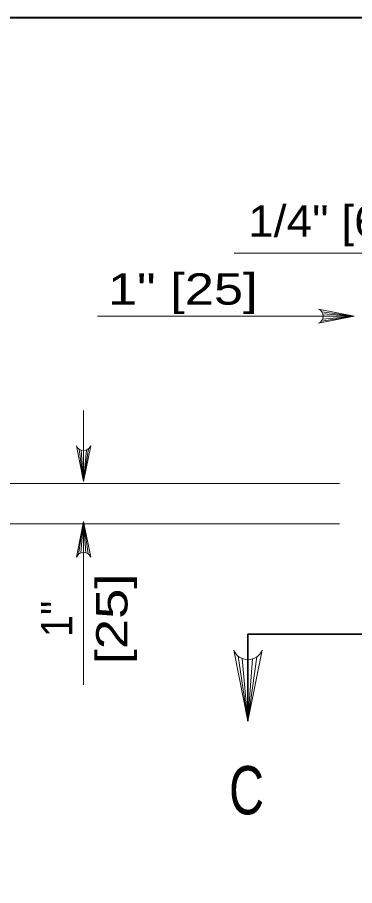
# Model space of a CAD drawing. Extents: x -410.5 to -376.5, y 1617.6 to 1661.6.
# Drawn here: x -396.459 to -394.78, y 1634.741 to 1639.062 of the extents above; entities that cross this region are included whole.
import ezdxf
from ezdxf.enums import TextEntityAlignment as Align

# ---------------------------------------------------------------- set-up
doc = ezdxf.new("R2010")
doc.units = 0
doc.header["$LTSCALE"] = 0.062
doc.layers.add('1', color=7, linetype='Continuous', lineweight=13)

msp = doc.modelspace()

# ---------------------------------------------------------------- linework, layer by layer
at = {"layer": '1', "lineweight": 25}
msp.add_line((-408.45475, 1639.06183), (-376.95475, 1639.06183), dxfattribs=at)
at = {"layer": '1'}
for p, q in [((-395.37925, 1637.88875), (-394.1165, 1637.88875)), ((-394.78308, 1637.57492), (-396.05983, 1637.57492)), ((-394.94525, 1637.55017), (-394.78308, 1637.57492)), ((-394.94333, 1637.59733), (-394.78308, 1637.57492)), ((-394.93908, 1637.56058), (-394.78308, 1637.57492)), ((-394.93792, 1637.58625), (-394.78308, 1637.57492)), ((-394.93625, 1637.57492), (-394.78308, 1637.57492)), ((-396.12908, 1636.75275), (-396.12908, 1637.10483)), ((-396.1515, 1636.913), (-396.12908, 1636.75275)), ((-396.14042, 1636.90758), (-396.12908, 1636.75275)), ((-396.10433, 1636.91483), (-396.12908, 1636.75275)), ((-396.11475, 1636.90875), (-396.12908, 1636.75275)), ((-396.12908, 1636.90592), (-396.12908, 1636.75275)), ((-400.65567, 1636.74175), (-394.85592, 1636.74175)), ((-400.65567, 1636.54183), (-394.85592, 1636.54183)), ((-396.15392, 1636.39075), (-396.12908, 1636.55283)), ((-396.1435, 1636.39683), (-396.12908, 1636.55283)), ((-396.12908, 1636.55283), (-396.12908, 1635.74108)), ((-396.12908, 1636.39967), (-396.12908, 1636.55283)), ((-396.11775, 1636.398), (-396.12908, 1636.55283)), ((-396.10667, 1636.39258), (-396.12908, 1636.55283)), ((-395.36058, 1635.88375), (-395.311, 1635.5595)), ((-395.33983, 1635.8715), (-395.311, 1635.5595)), ((-395.26617, 1635.88), (-395.311, 1635.5595)), ((-395.28833, 1635.86908), (-395.311, 1635.5595)), ((-395.311, 1635.86583), (-395.311, 1635.5595))]:
    msp.add_line(p, q, dxfattribs=at)
at = {"layer": '1', "lineweight": 35}
for q in [(-395.311, 1635.5595), (-393.8645, 1635.99217)]:
    msp.add_line((-395.311, 1635.99217), q, dxfattribs=at)
at = {"layer": '1', "lineweight": 40}
msp.add_lwpolyline([(-408.45475, 1639.06183), (-376.95475, 1639.06183), (-376.95475, 1618.06183), (-408.45475, 1618.06183)], close=True, dxfattribs=at)
msp.add_lwpolyline([(-408.45475, 1639.06183), (-376.95475, 1639.06183), (-376.95475, 1618.06183), (-408.45475, 1618.06183)], close=True, dxfattribs=at)
at = {"layer": '1'}
for points in [[(-394.96008, 1637.53958), (-394.78308, 1637.57492), (-394.96008, 1637.61033)], [(-396.09375, 1636.92975), (-396.12908, 1636.75275), (-396.1645, 1636.92975)], [(-396.1645, 1636.37583), (-396.12908, 1636.55283), (-396.09375, 1636.37583)], [(-395.38183, 1635.9135), (-395.311, 1635.5595), (-395.24025, 1635.9135)]]:
    msp.add_lwpolyline(points, dxfattribs=at)
for centre, radius, start, end in [((-394.97441, 1637.57499), 0.0382, 292.08605, 67.91218), ((-396.12915, 1636.94403), 0.0382, 202.08782, 337.91395), ((-396.12907, 1636.36155), 0.0382, 22.08782, 157.91395), ((-395.31095, 1635.94207), 0.0764, 202.08605, 337.91218)]:
    msp.add_arc(centre, radius, start, end, dxfattribs=at)

# ---------------------------------------------------------------- texts
for s, width, p in [('1/4" [6]', 1.1, (-395.3105, 1637.97025)), ('1" [25]', 1.25, (-396.008, 1637.63217))]:
    msp.add_text(s, height=0.156, dxfattribs=dict(at, width=width)).set_placement(p)
for s, width, p in [('[25]', 1.3, (-395.91075, 1636.06854)), ('1"', 0.95, (-396.18475, 1636.06854))]:
    msp.add_text(s, height=0.156, rotation=90, dxfattribs=dict(at, width=width)).set_placement(p, align=Align.CENTER)
at = {"layer": '1', "width": 0.75}
msp.add_text('C', height=0.24, dxfattribs=at).set_placement((-395.31808, 1635.09608), align=Align.CENTER)

doc.saveas('drawing.dxf')
